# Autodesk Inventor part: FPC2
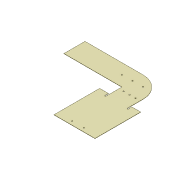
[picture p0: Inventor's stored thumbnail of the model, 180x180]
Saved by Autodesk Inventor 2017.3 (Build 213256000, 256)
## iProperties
Part Number: FPC2
Material: ポリプロピレン
Document SubType Name: Modeling
Designer: kyushu-hep
Density: 0.899 g/cm^3
Appearance: 滑らか - 灰色
Mass: 0.483015 g
Surface Area: 54.372 cm^2
Volume: 0.53728 cm^3
Author: kyushu-hep
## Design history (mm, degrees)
sketch "スケッチ1"
  geometry: L1 (-4.606, 13.906)-(-4.606, -25.094); L2 (-4.606, -25.094)-(30.394, -25.094); L3 (30.394, -25.094)-(30.394, 13.906); L4 (30.394, 13.906)-(22.894, 13.906); L5 (22.894, 13.906)-(22.894, 10.906); L6 (21.894, 10.906)-(21.894, 24.406); L7 (3.894, 42.406)-(-45.606, 42.406); L8 (-45.606, 42.406)-(-45.606, 24.406); L9 (-45.606, 24.406)-(3.894, 24.406); L10 (3.894, 24.406)-(3.894, 10.906); L11 (2.894, 10.906)-(2.894, 13.906); L12 (2.894, 13.906)-(-4.606, 13.906); A1 r 0.5 centre (22.394, 10.906) between (21.894, 10.906) and (22.894, 10.906); A2 r 18 centre (3.894, 24.406) between (21.894, 24.406) and (3.894, 42.406); A3 r 0.5 centre (3.394, 10.906) between (2.894, 10.906) and (3.894, 10.906); 1 further point
  constraints: 24 end point, 8 perpendicular, 6 point on circle, 6 tangent, 3 centre point, 3 equal length, 2 parallel, 1 horizontal, 1 vertical
  dimensions: "d0" = 39 distance of L1.start L1.end; "d1" = 35 distance of L1.end L2.end; "d2" = 39 distance of L2.end L3.end; "d3" = 13.5 distance of L6.start L6.end; "d4" = 0.5 distance from line of L10 A3.centre; "d5" = 0.5 distance from line of L6 A1.centre; "d6" = 18 distance between parallel lines of L6 L10; "d7" = 3 distance of L4.end L5.end; "d8" = 18 distance from line of L6 A2.centre; "d9" = 76 distance between parallel lines of L3 L8
extrude "押し出し1" new body sketch "スケッチ1" distance "d10" = 0.2; taper "d11" = 0 deg
sketch "スケッチ2"
  geometry: L1 (-4.606, -25.094)-(30.394, -25.094) reference; L2 (3.894, 24.406)-(3.894, 10.906) reference; L3 (-45.606, 24.406)-(3.894, 24.406) reference; C1 r 0.5 at (7.844, 21.906); C2 r 0.5 at (17.944, 21.906); C3 r 0.5 at (12.894, 21.906); C4 r 0.5 at (-5.106, 33.406); C5 r 0.5 at (3.894, 33.406); C6 r 0.5 at (12.894, 33.406); C7 r 0.5 at (7.844, -22.094); C8 r 0.5 at (17.944, -22.094); 1 further point
  constraints: 8 centre point
  dimensions: "d12" = 1 diameter of C1; "d13" = 1 diameter of C2; "d14" = 47 distance from line of C1.centre L1; "d15" = 47 distance from line of C2.centre L1; "d16" = 10.1 distance of C2.centre C1.centre; "d17" = 3.95 distance from line of C1.centre L2; "d20" = 1 diameter of C3; "d21" = 1 diameter of C4; "d22" = 1 diameter of C5; "d23" = 1 diameter of C6; "d24" = 1 diameter of C7; "d25" = 1 diameter of C8; "d26" = 10.1 distance of C8.centre C7.centre; "d27" = 3 distance from line of C7.centre L1; "d28" = 3 distance from line of L1 C8.centre; "d29" = 47 distance from line of L1 C3.centre; "d30" = 5.05 distance of C1.centre C3.centre; "d31" = 9 distance from line of L3 C4.centre; "d32" = 9 distance from line of L3 C5.centre; "d33" = 9 distance from line of L3 C6.centre; "d34" = 5.05 horizontal distance of C6.centre C1.centre; "d37" = 9 distance of C6.centre C5.centre; "d38" = 9 distance of C4.centre C5.centre
extrude "押し出し3" cut sketch "スケッチ2" distance "d35" = 0.2; taper "d36" = 0 deg
node "ソリッド1"
